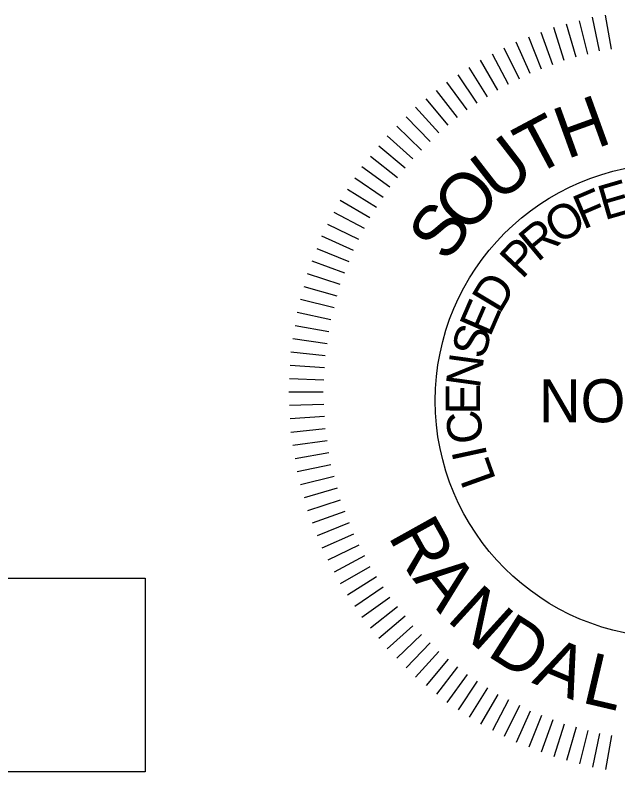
# Model space of a CAD drawing. Extents: x 1964849 to 1967422, y 1116563 to 1122211.
# Drawn here: x 1966326.3 to 1966388.6, y 1121678 to 1121756.2 of the extents above; entities that cross this region are included whole.
import ezdxf

# ---------------------------------------------------------------- set-up
doc = ezdxf.new("R2010")
doc.units = 0
doc.layers.add('RD_TX_Misc2', color=7, linetype='Continuous')
doc.layers.add('RD_TX_PEShield', color=7, linetype='Continuous')

msp = doc.modelspace()

# ---------------------------------------------------------------- linework, layer by layer
at = {"layer": 'RD_TX_Misc2'}
msp.add_lwpolyline([(1966176.293, 1121698.004), (1966339.734, 1121698.004), (1966339.734, 1121678.004), (1966176.293, 1121678.004)], close=True, dxfattribs=at)
at = {"layer": 'RD_TX_PEShield'}
for p, q in [((1966385.475, 1121752.147), (1966384.615, 1121755.597)), ((1966385.475, 1121752.147), (1966384.615, 1121755.597)), ((1966386.69, 1121752.473), (1966385.95, 1121755.955)), ((1966386.69, 1121752.473), (1966385.95, 1121755.955)), ((1966387.933, 1121752.67), (1966387.315, 1121756.171)), ((1966387.933, 1121752.67), (1966387.315, 1121756.171)), ((1966383.046, 1121751.496), (1966381.946, 1121754.882)), ((1966383.046, 1121751.496), (1966381.946, 1121754.882)), ((1966384.261, 1121751.822), (1966383.281, 1121755.24)), ((1966384.261, 1121751.822), (1966383.281, 1121755.24)), ((1966380.698, 1121750.595), (1966379.366, 1121753.892)), ((1966380.698, 1121750.595), (1966379.366, 1121753.892)), ((1966381.871, 1121751.045), (1966380.655, 1121754.387)), ((1966381.871, 1121751.045), (1966380.655, 1121754.387)), ((1966379.523, 1121750.144), (1966378.075, 1121753.396)), ((1966379.523, 1121750.144), (1966378.075, 1121753.396)), ((1966378.402, 1121749.573), (1966376.844, 1121752.769)), ((1966378.402, 1121749.573), (1966376.844, 1121752.769)), ((1966377.283, 1121749.003), (1966375.613, 1121752.142)), ((1966377.283, 1121749.003), (1966375.613, 1121752.142)), ((1966376.162, 1121748.431), (1966374.382, 1121751.514)), ((1966376.162, 1121748.431), (1966374.382, 1121751.514)), ((1966374.053, 1121747.062), (1966372.064, 1121750.01)), ((1966374.053, 1121747.062), (1966372.064, 1121750.01)), ((1966375.107, 1121747.746), (1966373.222, 1121750.762)), ((1966375.107, 1121747.746), (1966373.222, 1121750.762)), ((1966372.998, 1121746.377), (1966370.905, 1121749.257)), ((1966372.998, 1121746.377), (1966370.905, 1121749.257)), ((1966372.02, 1121745.585), (1966369.831, 1121748.387)), ((1966372.02, 1121745.585), (1966369.831, 1121748.387)), ((1966371.043, 1121744.794), (1966368.758, 1121747.518)), ((1966371.043, 1121744.794), (1966368.758, 1121747.518)), ((1966370.065, 1121744.002), (1966367.683, 1121746.648)), ((1966370.065, 1121744.002), (1966367.683, 1121746.648)), ((1966369.176, 1121743.113), (1966366.706, 1121745.67)), ((1966369.176, 1121743.113), (1966366.706, 1121745.67)), ((1966368.287, 1121742.224), (1966365.729, 1121744.694)), ((1966368.287, 1121742.224), (1966365.729, 1121744.694)), ((1966367.398, 1121741.334), (1966364.752, 1121743.716)), ((1966367.398, 1121741.334), (1966364.752, 1121743.716)), ((1966366.606, 1121740.357), (1966363.882, 1121742.642)), ((1966366.606, 1121740.357), (1966363.882, 1121742.642)), ((1966365.815, 1121739.38), (1966363.013, 1121741.569)), ((1966365.815, 1121739.38), (1966363.013, 1121741.569)), ((1966365.023, 1121738.402), (1966362.143, 1121740.495)), ((1966365.023, 1121738.402), (1966362.143, 1121740.495)), ((1966364.338, 1121737.347), (1966361.39, 1121739.335)), ((1966364.338, 1121737.347), (1966361.39, 1121739.335)), ((1966363.654, 1121736.293), (1966360.638, 1121738.177)), ((1966363.654, 1121736.293), (1966360.638, 1121738.177)), ((1966362.968, 1121735.238), (1966359.885, 1121737.018)), ((1966362.968, 1121735.238), (1966359.885, 1121737.018)), ((1966362.397, 1121734.117), (1966359.258, 1121735.786)), ((1966362.397, 1121734.117), (1966359.258, 1121735.786)), ((1966361.827, 1121732.997), (1966358.631, 1121734.556)), ((1966361.827, 1121732.997), (1966358.631, 1121734.556)), ((1966361.255, 1121731.876), (1966358.003, 1121733.324)), ((1966361.255, 1121731.876), (1966358.003, 1121733.324)), ((1966360.805, 1121730.702), (1966357.508, 1121732.034)), ((1966360.805, 1121730.702), (1966357.508, 1121732.034)), ((1966360.354, 1121729.529), (1966357.013, 1121730.745)), ((1966360.354, 1121729.529), (1966357.013, 1121730.745)), ((1966359.903, 1121728.354), (1966356.518, 1121729.454)), ((1966359.903, 1121728.354), (1966356.518, 1121729.454)), ((1966359.578, 1121727.139), (1966356.16, 1121728.119)), ((1966359.578, 1121727.139), (1966356.16, 1121728.119)), ((1966359.253, 1121725.925), (1966355.802, 1121726.785)), ((1966359.253, 1121725.925), (1966355.802, 1121726.785)), ((1966358.927, 1121724.71), (1966355.445, 1121725.45)), ((1966358.927, 1121724.71), (1966355.445, 1121725.45)), ((1966358.73, 1121723.467), (1966355.228, 1121724.084)), ((1966358.73, 1121723.467), (1966355.228, 1121724.084)), ((1966358.534, 1121722.226), (1966355.012, 1121722.721)), ((1966358.534, 1121722.226), (1966355.012, 1121722.721)), ((1966358.337, 1121720.983), (1966354.796, 1121721.355)), ((1966358.337, 1121720.983), (1966354.796, 1121721.355)), ((1966358.271, 1121719.727), (1966354.724, 1121719.975)), ((1966358.271, 1121719.727), (1966354.724, 1121719.975)), ((1966358.205, 1121718.472), (1966354.652, 1121718.596)), ((1966358.205, 1121718.472), (1966354.652, 1121718.596)), ((1966358.139, 1121717.216), (1966354.579, 1121717.216)), ((1966358.139, 1121717.216), (1966354.579, 1121717.216)), ((1966358.205, 1121715.959), (1966354.652, 1121715.835)), ((1966358.205, 1121715.959), (1966354.652, 1121715.835)), ((1966358.271, 1121714.704), (1966354.724, 1121714.456)), ((1966358.271, 1121714.704), (1966354.724, 1121714.456)), ((1966358.337, 1121713.448), (1966354.796, 1121713.076)), ((1966358.337, 1121713.448), (1966354.796, 1121713.076)), ((1966358.534, 1121712.205), (1966355.012, 1121711.71)), ((1966358.534, 1121712.205), (1966355.012, 1121711.71)), ((1966358.73, 1121710.964), (1966355.228, 1121710.347)), ((1966358.73, 1121710.964), (1966355.228, 1121710.347)), ((1966358.927, 1121709.721), (1966355.445, 1121708.981)), ((1966358.927, 1121709.721), (1966355.445, 1121708.981)), ((1966359.253, 1121708.506), (1966355.802, 1121707.646)), ((1966359.253, 1121708.506), (1966355.802, 1121707.646)), ((1966359.578, 1121707.292), (1966356.16, 1121706.312)), ((1966359.578, 1121707.292), (1966356.16, 1121706.312)), ((1966359.903, 1121706.077), (1966356.518, 1121704.977)), ((1966360.354, 1121704.902), (1966357.013, 1121703.686)), ((1966360.354, 1121704.902), (1966357.013, 1121703.686)), ((1966360.805, 1121703.729), (1966357.508, 1121702.397)), ((1966360.805, 1121703.729), (1966357.508, 1121702.397)), ((1966361.255, 1121702.555), (1966358.003, 1121701.107)), ((1966361.255, 1121702.555), (1966358.003, 1121701.107)), ((1966361.827, 1121701.434), (1966358.631, 1121699.875)), ((1966361.827, 1121701.434), (1966358.631, 1121699.875)), ((1966362.397, 1121700.314), (1966359.258, 1121698.645)), ((1966362.397, 1121700.314), (1966359.258, 1121698.645)), ((1966362.968, 1121699.193), (1966359.885, 1121697.413)), ((1966362.968, 1121699.193), (1966359.885, 1121697.413)), ((1966363.654, 1121698.138), (1966360.638, 1121696.254)), ((1966363.654, 1121698.138), (1966360.638, 1121696.254)), ((1966364.338, 1121697.084), (1966361.39, 1121695.096)), ((1966364.338, 1121697.084), (1966361.39, 1121695.096)), ((1966365.023, 1121696.029), (1966362.143, 1121693.936)), ((1966365.023, 1121696.029), (1966362.143, 1121693.936)), ((1966365.815, 1121695.051), (1966363.013, 1121692.862)), ((1966365.815, 1121695.051), (1966363.013, 1121692.862)), ((1966366.606, 1121694.074), (1966363.882, 1121691.789)), ((1966366.606, 1121694.074), (1966363.882, 1121691.789)), ((1966367.398, 1121693.097), (1966364.752, 1121690.715)), ((1966367.398, 1121693.097), (1966364.752, 1121690.715)), ((1966368.287, 1121692.207), (1966365.729, 1121689.737)), ((1966368.287, 1121692.207), (1966365.729, 1121689.737)), ((1966369.176, 1121691.319), (1966366.706, 1121688.761)), ((1966369.176, 1121691.319), (1966366.706, 1121688.761)), ((1966370.065, 1121690.429), (1966367.683, 1121687.783)), ((1966370.065, 1121690.429), (1966367.683, 1121687.783)), ((1966371.043, 1121689.637), (1966368.758, 1121686.913)), ((1966371.043, 1121689.637), (1966368.758, 1121686.913)), ((1966372.02, 1121688.846), (1966369.831, 1121686.044)), ((1966372.02, 1121688.846), (1966369.831, 1121686.044)), ((1966372.998, 1121688.054), (1966370.905, 1121685.174)), ((1966372.998, 1121688.054), (1966370.905, 1121685.174)), ((1966374.053, 1121687.369), (1966372.064, 1121684.421)), ((1966374.053, 1121687.369), (1966372.064, 1121684.421)), ((1966375.107, 1121686.685), (1966373.222, 1121683.669)), ((1966375.107, 1121686.685), (1966373.222, 1121683.669)), ((1966376.162, 1121686), (1966374.382, 1121682.917)), ((1966376.162, 1121686), (1966374.382, 1121682.917)), ((1966377.283, 1121685.428), (1966375.613, 1121682.289)), ((1966377.283, 1121685.428), (1966375.613, 1121682.289)), ((1966378.402, 1121684.858), (1966376.844, 1121681.662)), ((1966378.402, 1121684.858), (1966376.844, 1121681.662)), ((1966379.523, 1121684.287), (1966378.075, 1121681.035)), ((1966379.523, 1121684.287), (1966378.075, 1121681.035)), ((1966380.698, 1121683.836), (1966379.366, 1121680.539)), ((1966380.698, 1121683.836), (1966379.366, 1121680.539)), ((1966381.871, 1121683.386), (1966380.655, 1121680.044)), ((1966381.871, 1121683.386), (1966380.655, 1121680.044)), ((1966383.046, 1121682.935), (1966381.946, 1121679.549)), ((1966383.046, 1121682.935), (1966381.946, 1121679.549)), ((1966384.261, 1121682.609), (1966383.281, 1121679.191)), ((1966384.261, 1121682.609), (1966383.281, 1121679.191)), ((1966385.475, 1121682.284), (1966384.615, 1121678.834)), ((1966385.475, 1121682.284), (1966384.615, 1121678.834)), ((1966386.69, 1121681.958), (1966385.95, 1121678.476)), ((1966386.69, 1121681.958), (1966385.95, 1121678.476)), ((1966387.933, 1121681.761), (1966387.315, 1121678.26)), ((1966387.933, 1121681.761), (1966387.315, 1121678.26))]:
    msp.add_line(p, q, dxfattribs=at)
msp.add_circle((1966394.184, 1121716.337), 24.475, dxfattribs=at)

# ---------------------------------------------------------------- texts
for s, height, rotation, p in [('H', 5.34, 19.91024, (1966383.28, 1121741.259)), ('T', 5.34, 28.09472, (1966379.843, 1121739.453)), ('U', 5.34, 37.77255, (1966376.162, 1121736.713)), ('O', 5.34, 47.45038, (1966372.993, 1121733.393)), ('E', 3.56, 16.18428, (1966387.182, 1121734.971)), ('F', 3.56, 23.08525, (1966384.994, 1121733.995)), ('O', 3.56, 31.78688, (1966382.428, 1121732.401)), ('S', 5.34, 54.90268, (1966370.96, 1121730.501)), ('R', 3.56, 39.89024, (1966380.281, 1121730.584)), ('P', 3.56, 46.7912, (1966378.67, 1121728.81)), ('D', 3.56, 59.07401, (1966376.372, 1121725.224)), ('E', 3.56, 66.56738, (1966375.365, 1121722.826)), ('S', 3.56, 73.46834, (1966374.722, 1121720.517)), ('N', 3.56, 82.16997, (1966374.314, 1121717.525)), ('E', 3.56, 89.66334, (1966374.328, 1121714.923)), ('C', 3.56, 97.7667, (1966374.726, 1121712.139)), ('I', 3.56, 102.25114, (1966375.114, 1121710.63)), ('L', 3.56, 109.74451, (1966376.021, 1121708.192)), ('R', 5.34, 299.14926, (1966364.782, 1121702.364)), ('A', 5.34, 308.08766, (1966367.31, 1121697.965)), ('N', 5.34, 317.7655, (1966370.781, 1121693.709)), ('D', 5.34, 327.44333, (1966374.918, 1121690.097)), ('A', 5.34, 337.12116, (1966379.604, 1121687.231)), ('L', 5.34, 346.799, (1966384.704, 1121685.194))]:
    msp.add_text(s, height=height, rotation=rotation, dxfattribs=at).set_placement(p)
msp.add_text('NO. 24265', height=4.4501, dxfattribs=at).set_placement((1966380.43, 1121714.112))

doc.saveas('drawing.dxf')
